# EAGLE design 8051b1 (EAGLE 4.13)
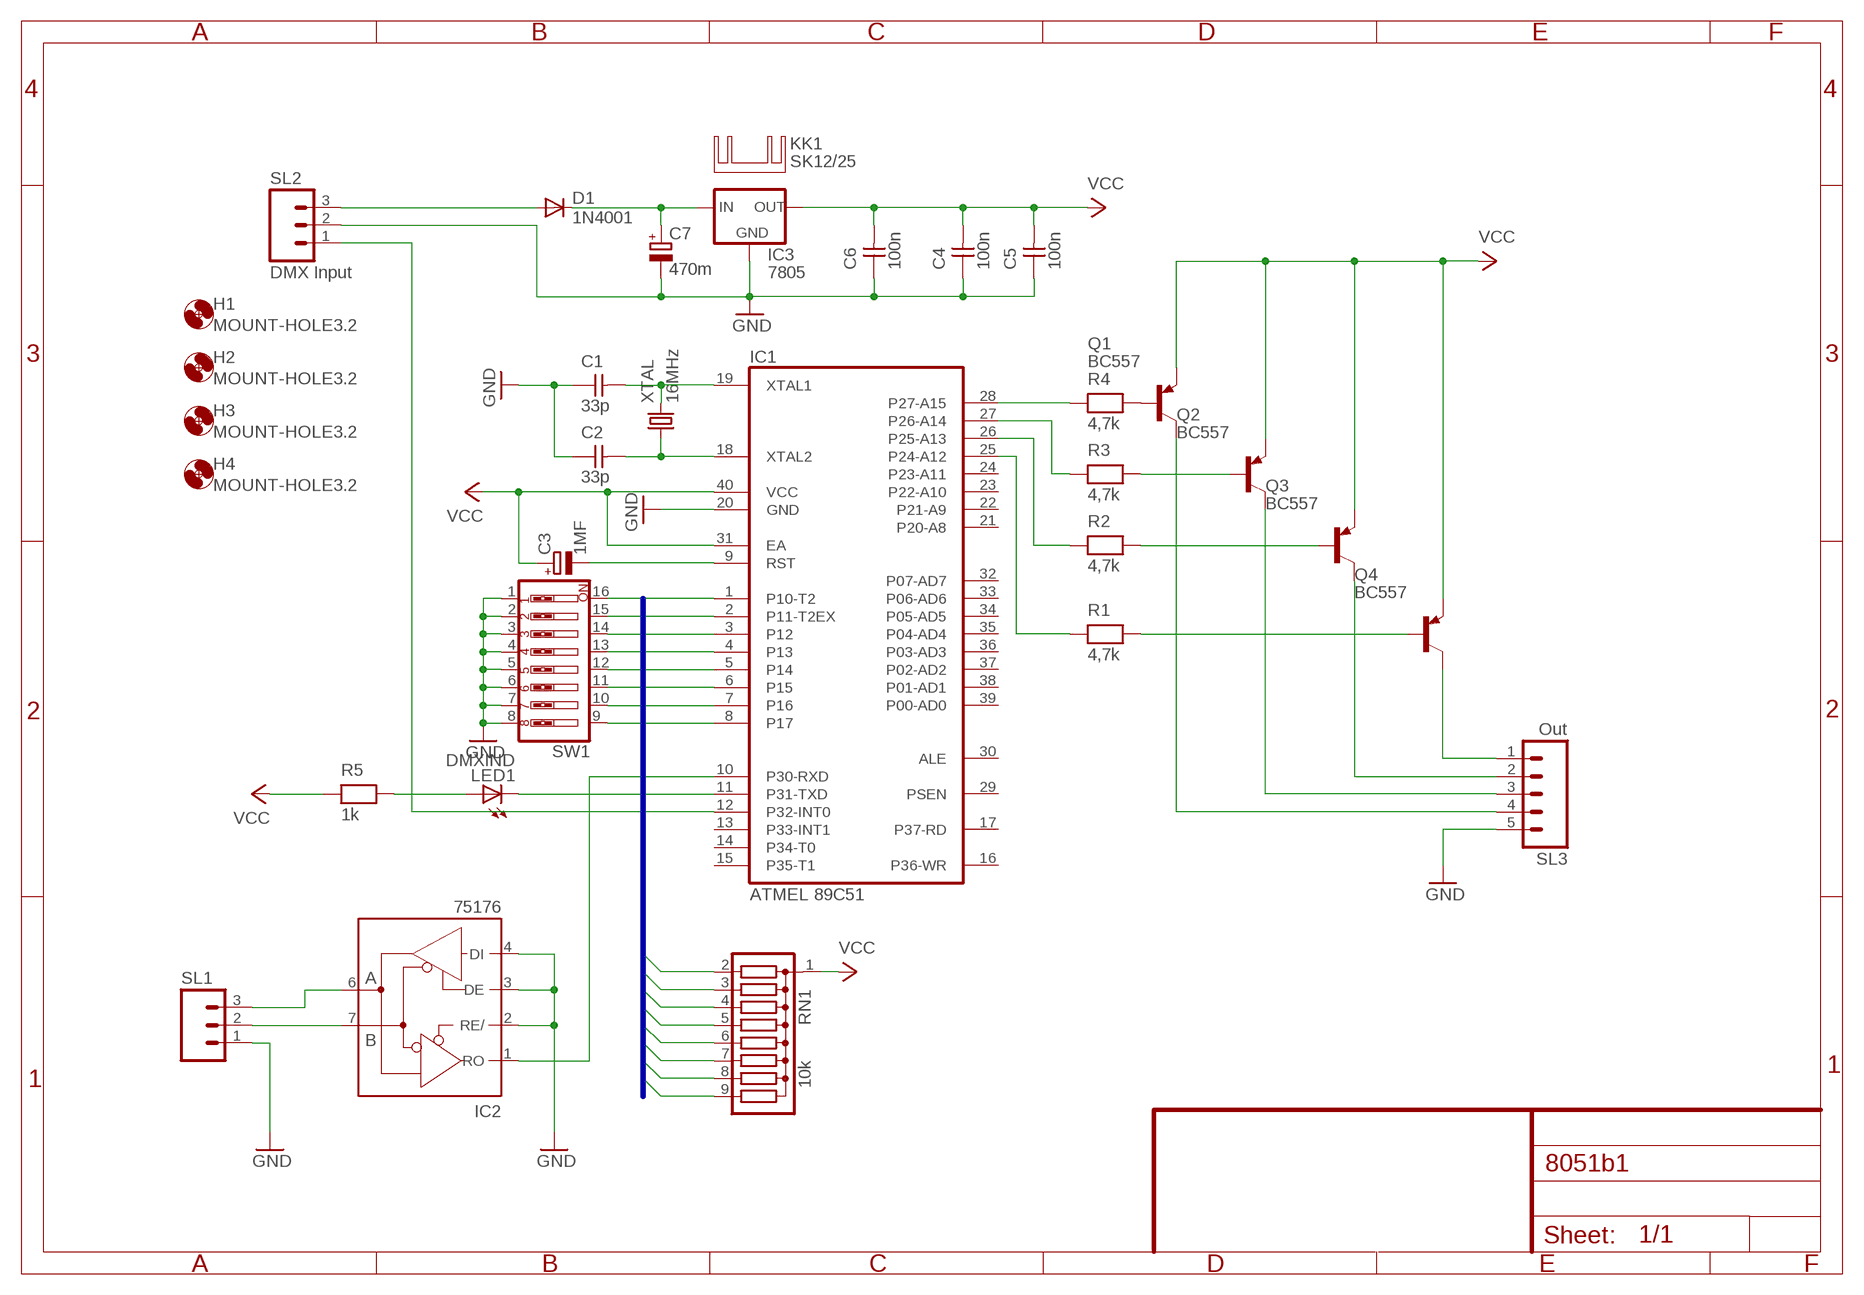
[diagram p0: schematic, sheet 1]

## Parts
C1  33p  CAPNP-5  [C-5]
C2  33p  CAPNP-5  [C-5]
C3  1MF  CPOL-EUE2-4  [E2-4]
C4  100n  CAPNP-2,5  [C-2,5]
C5  100n  CAPNP-2,5  [C-2,5]
C6  100n  CAPNP-2,5  [C-2,5]
C7  470m  CPOL-EUE5-10.5  [E5-10,5]
D1  1N4001  1N4004  [DO41-10]
H1  MOUNT-HOLE3.2  [3,2]
H2  MOUNT-HOLE3.2  [3,2]
H3  MOUNT-HOLE3.2  [3,2]
H4  MOUNT-HOLE3.2  [3,2]
IC1  ATMEL 89C51  8051  [DIL40]
IC2  75176  MAX481CPA  [DIL08]
IC3  7805  78XXL  [78XXL]
KK1  SK12/25  [SK12/25]
LED1  DMXIND  LED3MM  [LED3MM]
Q1  BC557  [TO92]
Q2  BC557  [TO92]
Q3  BC557  [TO92]
Q4  BC557  [TO92]
R1  4,7k  RESEU-10  [R-10]
R2  4,7k  RESEU-10  [R-10]
R3  4,7k  RESEU-10  [R-10]
R4  4,7k  RESEU-10  [R-10]
R5  1k  RESEU-10  [R-10]
RN1  10k  G08R  [SIL9]
SL1  M03  [03P]
SL2  DMX Input  M03  [03P]
SL3  Out  M05  [05P]
SW1  SW_DIP-8  [EDG-08]
XTAL  16MHz  CRYTALHC18U-V  [HC18U-V]

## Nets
DIP1: IC1.1(P10-T2) RN1.2 SW1.16
DIP2: IC1.2(P11-T2EX) RN1.3 SW1.15
DIP3: IC1.3(P12) RN1.4 SW1.14
DIP4: IC1.4(P13) RN1.5 SW1.13
DIP5: IC1.5(P14) RN1.6 SW1.12
DIP6: IC1.6(P15) RN1.7 SW1.11
DIP7: IC1.7(P16) RN1.8 SW1.10
DIP8: IC1.8(P17) RN1.9 SW1.9
DMX+: IC2.6(A) SL1.3
DMX-: IC2.7(B) SL1.2
DMXIND: IC1.11(P31-TXD) LED1.K(C)
EXT0: IC1.12(P32-INT0) SL2.1
GND: C1.1 C2.1 C4.1 C5.1 C6.1 C7.- IC1.20(GND) IC2.2(RE/) IC2.3(DE) IC2.4(DI) IC3.GND SL1.1 SL2.2 SL3.5 SW1.1 SW1.2 SW1.3 SW1.4 SW1.5 SW1.6 SW1.7 SW1.8
N$1: C1.2 IC1.19(XTAL1) XTAL.2
N$2: C2.2 IC1.18(XTAL2) XTAL.1
N$3: Q1.2(B) R4.2
N$4: LED1.A R5.2
N$13: C7.+ D1.C IC3.IN
N$14: D1.A SL2.3
N$19: Q2.2(B) R3.2
N$20: Q3.2(B) R2.2
N$21: Q4.2(B) R1.2
OUT1: IC1.25(P24-A12) R1.1
OUT2: IC1.26(P25-A13) R2.1
OUT3: IC1.27(P26-A14) R3.1
OUT4: IC1.28(P27-A15) R4.1
RESET: C3.- IC1.9(RST)
RXD: IC1.10(P30-RXD) IC2.1(RO)
TREIBEROUT1: Q4.3(C) SL3.1
TREIBEROUT2: Q3.3(C) SL3.2
TREIBEROUT3: Q2.3(C) SL3.3
TREIBEROUT4: Q1.3(C) SL3.4
VCC: C3.+ C4.2 C5.2 C6.2 IC1.31(EA) IC1.40(VCC) IC3.OUT Q1.1(E) Q2.1(E) Q3.1(E) Q4.1(E) R5.1 RN1.1
Unconnected: IC1.13(P33-INT1) IC1.14(P34-T0) IC1.15(P35-T1) IC1.16(P36-WR) IC1.17(P37-RD) IC1.21(P20-A8) IC1.22(P21-A9) IC1.23(P22-A10) IC1.24(P23-A11) IC1.29(PSEN) IC1.30(ALE) IC1.32(P07-AD7) IC1.33(P06-AD6) IC1.34(P05-AD5) IC1.35(P04-AD4) IC1.36(P03-AD3) IC1.37(P02-AD2) IC1.38(P01-AD1) IC1.39(P00-AD0)

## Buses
B$1

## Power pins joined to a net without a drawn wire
GND: IC2.5(GND)
VCC: IC2.8(VCC)

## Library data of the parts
C1 C2 = discrete:CAPNP-5
C3 C7 = rcl:CPOL-EU: POLARIZED CAPACITOR, European symbol
C4-C6 = discrete:CAPNP-2,5
D1 = diode:1N4004: DIODE
H1-H4 = holes:MOUNT-HOLE: MOUNTING HOLE with drill center marker
IC1 = micro-intel:8051: MICROCOMPUTER/PERIPHERAL DEVICE
IC2 = maxim:MAX481CPA: RS485 TRANSEIVER
IC3 = v-reg:78XXL: VOLTAGE REGULATOR
KK1 = heatsink:SK12/25: HEATSINK
LED1 = led:LED: LED
Q1-Q4 = transistor-pnp:BC557: PNP Transistor
R1-R5 = discrete:RESEU-10
RN1 = resistor-sil:G08R: SIL RESISTOR
SL1 SL2 = con-amp-quick:M03: AMP QUICK CONNECTOR
SL3 = con-amp-quick:M05: AMP QUICK CONNECTOR
SW1 = special:SW_DIP-8: DIP SWITCH
XTAL = crystal:CRYTAL: CRYSTAL

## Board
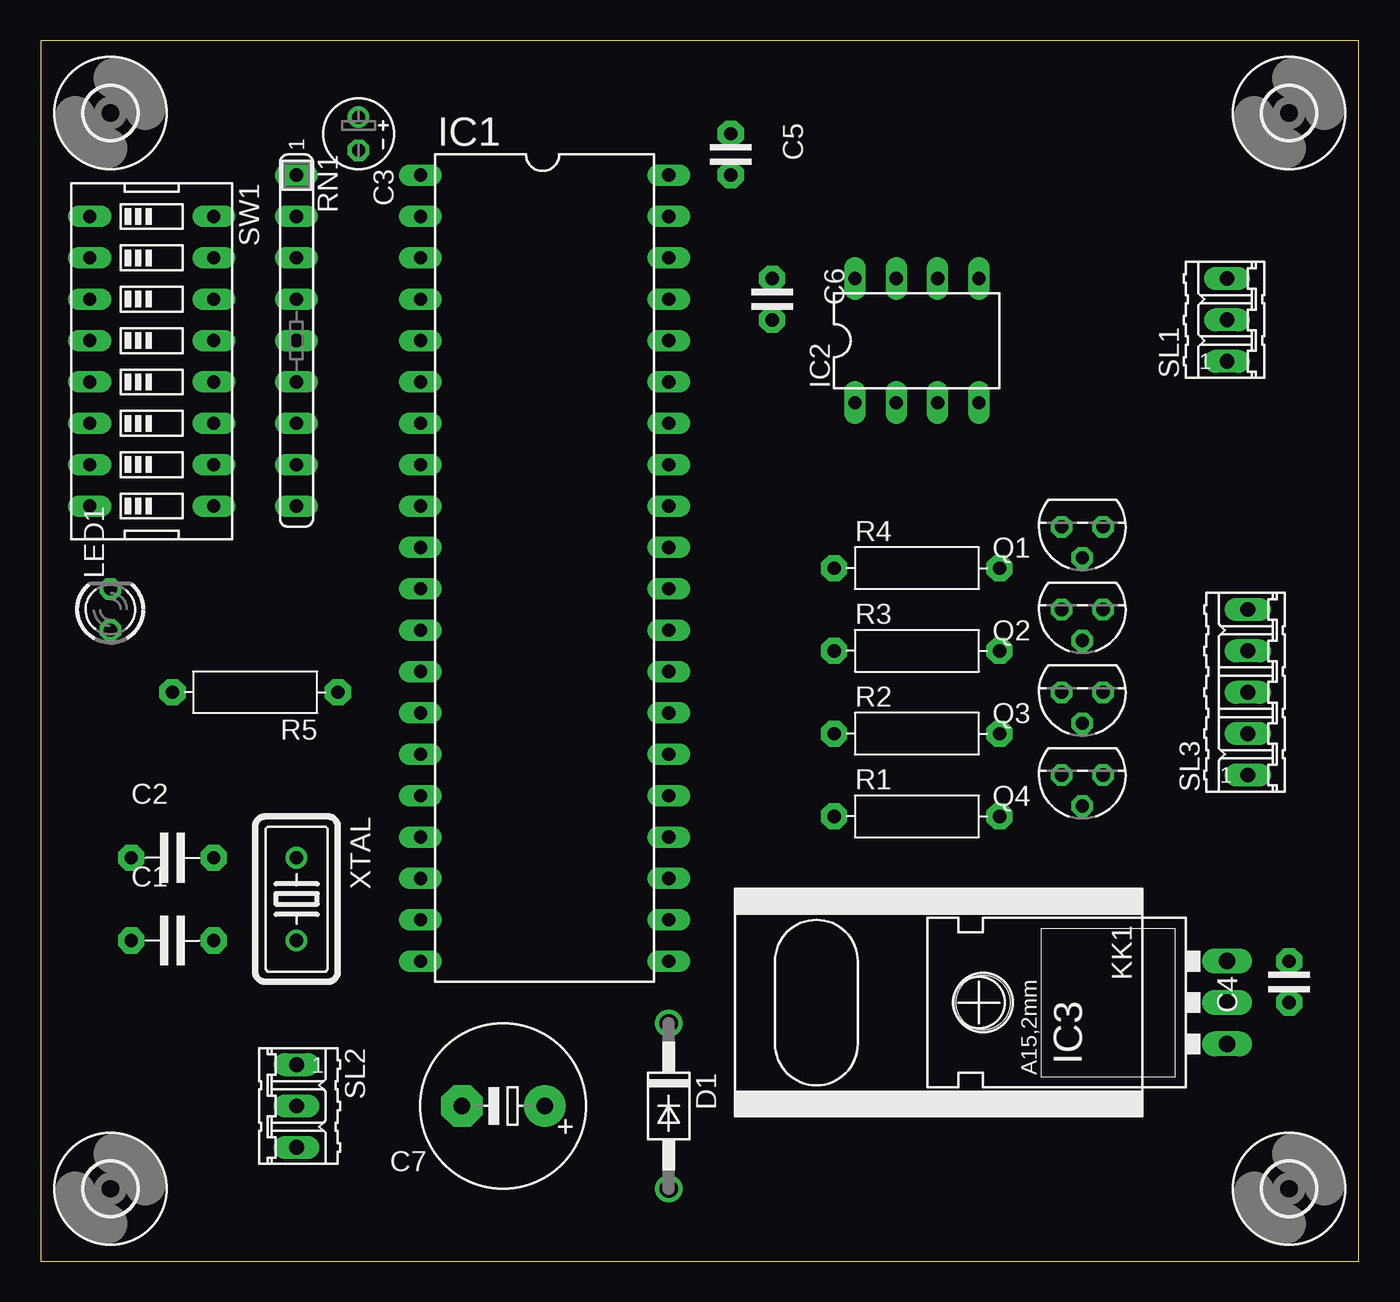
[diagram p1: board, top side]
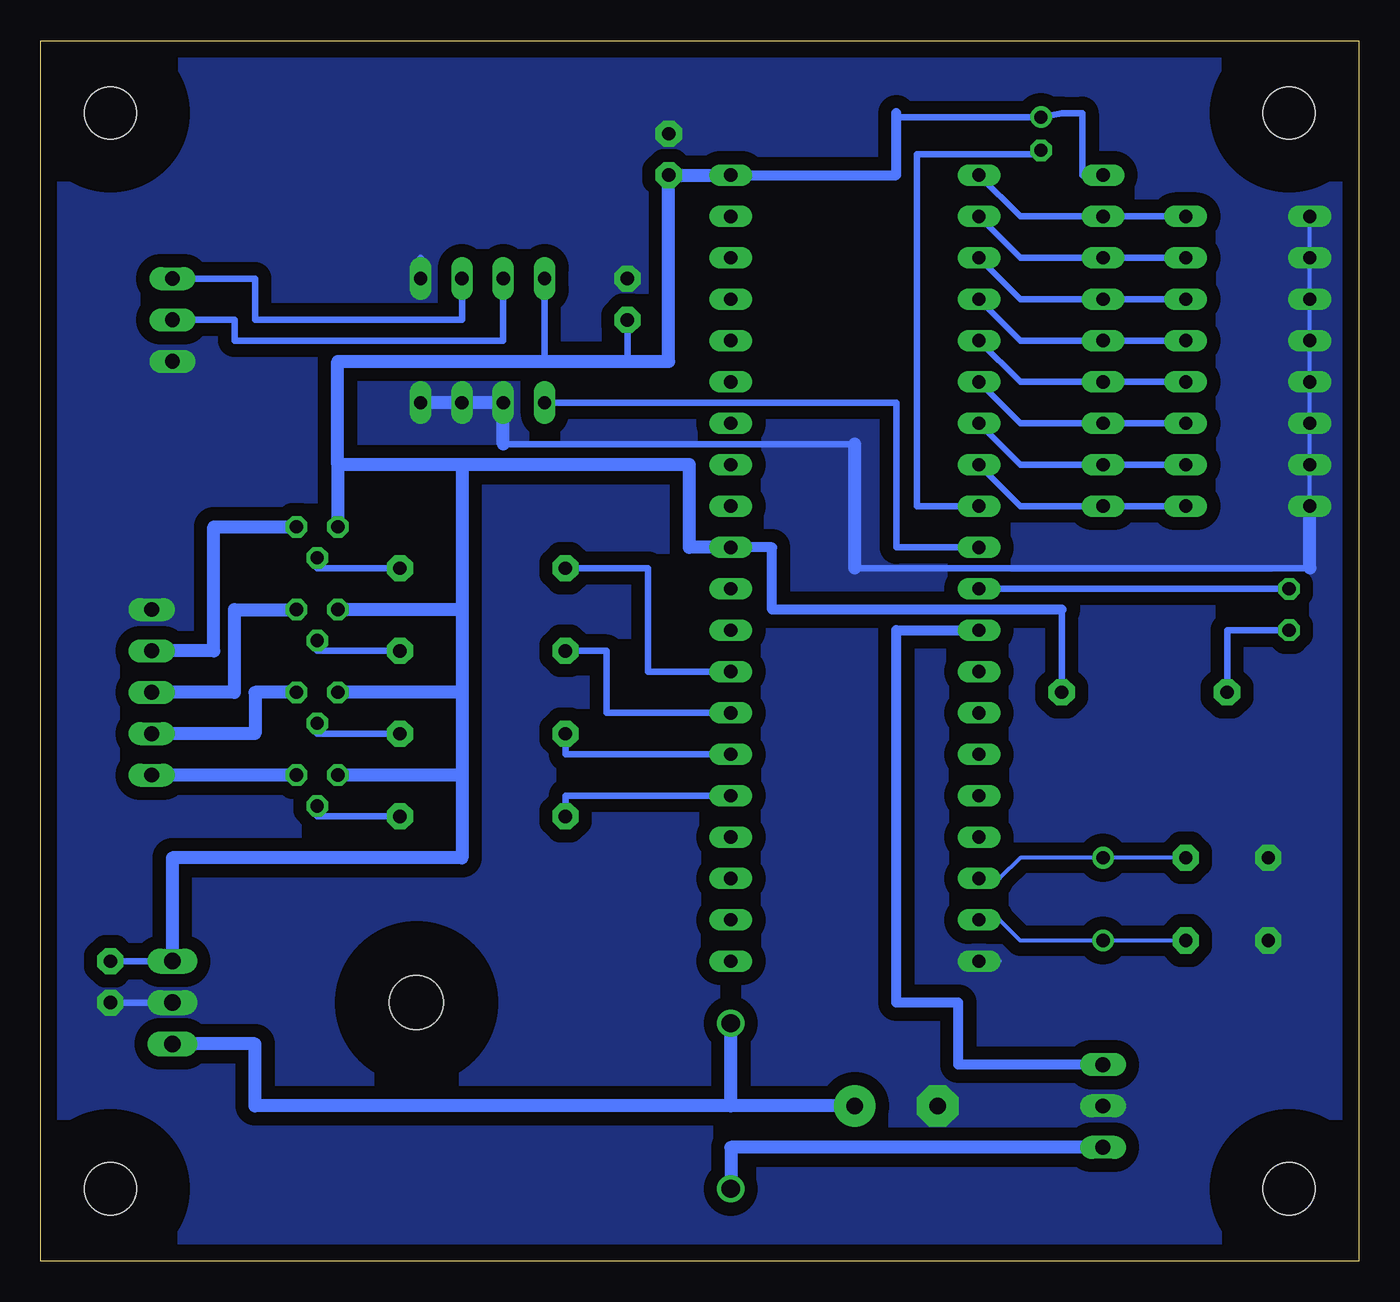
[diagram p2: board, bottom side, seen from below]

Size 80.95 x 74.92 mm. Coordinates in mm from the lower left corner, seen from the top.
Outline: 0,0 80.95,0 80.95,74.92 0,74.92 0,0
Copper layers (1*16): Top 0.035mm / dielectric 1.5mm / Bottom 0.035mm
Design rules "default": minimum track width 10mil, minimum drill 24mil, track to track 8mil, track to pad 8mil, pad to pad 8mil, via to via 8mil, smd to smd 8mil, copper to edge 40mil, drill to drill 8mil, minimum pad ring 10mil, minimum via ring 8mil, stop-mask expansion 4mil, vias tented up to drill 0mil, thermal gap 10mil

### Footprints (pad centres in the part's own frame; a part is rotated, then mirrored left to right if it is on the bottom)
C-5 = drill 0.813 pad 1.6 octagon: 1 -2.54,0; 2 2.54,0
E2-4 = drill 0.813 pad 1.27 round: + -1.016,0 | drill 0.813 pad 1.27 octagon: - 1.016,0
C-2,5 = drill 0.813 pad 1.6 octagon: 1 -1.27,0; 2 1.27,0
E5-10,5 = drill 1.016 pad 2.54 round: + -2.54,0 | drill 1.016 pad 2.54 octagon: - 2.54,0
DO41-10 = drill 1.118 round: A 5.08,0; C -5.08,0
3,2 = hole 3.2: 0,0
DIL40 = drill 0.813 long: 1 -24.13,-7.62; 2 -21.59,-7.62; 3 -19.05,-7.62; 4 -16.51,-7.62; 5 -13.97,-7.62; 6 -11.43,-7.62; 7 -8.89,-7.62; 8 -6.35,-7.62; 9 -3.81,-7.62; 10 -1.27,-7.62; 11 1.27,-7.62; 12 3.81,-7.62; 13 6.35,-7.62; 14 8.89,-7.62; 15 11.43,-7.62; 16 13.97,-7.62; 17 16.51,-7.62; 18 19.05,-7.62; 19 21.59,-7.62; 20 24.13,-7.62; 21 24.13,7.62; 22 21.59,7.62; 23 19.05,7.62; 24 16.51,7.62; 25 13.97,7.62; 26 11.43,7.62; 27 8.89,7.62; 28 6.35,7.62; 29 3.81,7.62; 30 1.27,7.62; 31 -1.27,7.62; 32 -3.81,7.62; 33 -6.35,7.62; 34 -8.89,7.62; 35 -11.43,7.62; 36 -13.97,7.62; 37 -16.51,7.62; 38 -19.05,7.62; 39 -21.59,7.62; 40 -24.13,7.62
DIL08 = drill 0.813 long: 1 -3.81,-3.81; 2 -1.27,-3.81; 3 1.27,-3.81; 4 3.81,-3.81; 5 3.81,3.81; 6 1.27,3.81; 7 -1.27,3.81; 8 -3.81,3.81
78XXL = drill 1.016 long: GND 0,-3.81; IN -2.54,-3.81; OUT 2.54,-3.81 | hole 3.302: 0,11.176
LED3MM = drill 0.813 octagon: A -1.27,0; K 1.27,0
TO92 = drill 0.813 octagon: 1 1.27,0; 2 0,1.905; 3 -1.27,0
R-10 = drill 0.813 pad 1.6 octagon: 1 -5.08,0; 2 5.08,0
SIL9 = drill 0.813 long: 1 -10.16,0; 2 -7.62,0; 3 -5.08,0; 4 -2.54,0; 5 0,0; 6 2.54,0; 7 5.08,0; 8 7.62,0; 9 10.16,0
03P = drill 0.914 long: 1 -2.54,0; 2 0,0; 3 2.54,0
05P = drill 0.914 long: 1 -5.08,0; 2 -2.54,0; 3 0,0; 4 2.54,0; 5 5.08,0
EDG-08 = drill 0.813 long: 1 -8.89,-3.81; 2 -6.35,-3.81; 3 -3.81,-3.81; 4 -1.27,-3.81; 5 1.27,-3.81; 6 3.81,-3.81; 7 6.35,-3.81; 8 8.89,-3.81; 9 8.89,3.81; 10 6.35,3.81; 11 3.81,3.81; 12 1.27,3.81; 13 -1.27,3.81; 14 -3.81,3.81; 15 -6.35,3.81; 16 -8.89,3.81
HC18U-V = drill 0.813 round: 1 -2.54,0; 2 2.54,0

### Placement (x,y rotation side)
C1  8.09,19.68 0 top
C2  8.09,24.76 0 top
C3  19.52,69.21 270 top
C4  76.67,17.14 90 top
C5  42.38,67.94 270 top
C6  44.92,59.05 270 top
C7  28.41,9.52 180 top
D1  38.57,9.52 270 top
H1  4.28,4.44 0 top
H2  4.28,70.48 0 top
H3  76.67,70.48 0 top
H4  76.67,4.44 0 top
IC1  30.95,42.54 270 top
IC2  53.81,56.51 0 top
IC3  69.05,15.87 90 top
KK1  52.54,15.87 180 top
LED1  4.28,40 90 top
Q1  63.97,45.08 180 top
Q2  63.97,40 180 top
Q3  63.97,34.92 180 top
Q4  63.97,29.84 180 top
R1  53.81,27.3 0 top
R2  53.81,32.38 0 top
R3  53.81,37.46 0 top
R4  53.81,42.54 0 top
R5  13.17,34.92 180 top
RN1  15.71,56.51 270 top
SL1  72.86,57.78 90 top
SL2  15.71,9.52 270 top
SL3  74.13,34.92 90 top
SW1  6.82,55.24 270 top
XTAL  15.71,22.22 270 top

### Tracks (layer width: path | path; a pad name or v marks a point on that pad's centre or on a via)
DIP1
  Bottom 0.406: IC1.1 20.79,64.13 RN1.2 SW1.16
DIP2
  Bottom 0.406: IC1.2 20.79,61.59 RN1.3 SW1.15
DIP3
  Bottom 0.406: IC1.3 20.79,59.05 RN1.4 SW1.14
DIP4
  Bottom 0.406: IC1.4 20.79,56.51 RN1.5 SW1.13
DIP5
  Bottom 0.406: IC1.5 20.79,53.97 RN1.6 SW1.12
DIP6
  Bottom 0.406: IC1.6 20.79,51.43 RN1.7 SW1.11
DIP7
  Bottom 0.406: IC1.7 20.79,48.89 RN1.8 SW1.10
DIP8
  Bottom 0.406: SW1.9 RN1.9 20.79,46.35 IC1.8
DMX+
  Bottom 0.406: SL1.3 67.78,60.32 67.78,57.78 55.08,57.78 IC2.6
DMX-
  Bottom 0.406: SL1.2 69.05,57.78 69.05,56.51 52.54,56.51 IC2.7
DMXIND
  Bottom 0.406: LED1.K IC1.11
EXT0
  Bottom 0.61: SL2.1 24.6,12.06 24.6,15.87 28.41,15.87 28.41,38.73 IC1.12
GND
  Bottom 0.254: SW1.1 SW1.2 SW1.3 SW1.4 SW1.5 SW1.6 SW1.7 SW1.8 | IC1.20 22.06,18.41
  Bottom 0.406: IC3.GND C4.1 | 30.95,50.16 52.54,50.16 | 3.01,42.54 30.95,42.54 | IC2.5 57.62,61.59
  Bottom 0.813: 52.54,50.16 IC2.2 IC2.3 IC2.4 | 30.95,42.54 30.95,50.16 | 3.01,42.54 SW1.8
  pour Bottom (isolate 0.813, no thermals): 1.74,74.29 80.48,74.29 80.48,0.63 0.47,0.63 0.47,74.29
N$1
  Bottom 0.254: C1.2 XTAL.2 20.79,19.68 22.06,20.95 IC1.19
N$2
  Bottom 0.254: C2.2 XTAL.1 20.79,24.76 22.06,23.49 IC1.18
N$3
  Bottom 0.406: Q1.2 63.97,42.54 R4.2
N$4
  Bottom 0.406: LED1.A 8.09,38.73 R5.2
N$13
  Bottom 0.813: 38.57,9.52 67.78,9.52 67.78,13.33 IC3.IN | C7.+ 38.57,9.52 | 38.57,9.52 D1.C
N$14
  Bottom 0.813: D1.A 38.57,6.98 SL2.3
N$19
  Bottom 0.406: Q2.2 63.97,37.46 R3.2
N$20
  Bottom 0.406: R2.2 63.97,32.38 Q3.2
N$21
  Bottom 0.406: Q4.2 63.97,27.3 R1.2
OUT1
  Bottom 0.406: IC1.25 48.73,28.57 R1.1
OUT2
  Bottom 0.406: IC1.26 48.73,31.11 R2.1
OUT3
  Bottom 0.406: IC1.27 46.19,33.65 46.19,37.46 R3.1
OUT4
  Bottom 0.406: IC1.28 43.65,36.19 43.65,42.54 R4.1
RESET
  Bottom 0.254: IC1.9 24.6,46.35
  Bottom 0.406: IC1.9 27.14,46.35 27.14,67.94 19.52,67.94 C3.-
RXD
  Bottom 0.406: IC2.1 28.41,52.7 28.41,43.81 IC1.10
TREIBEROUT1
  Bottom 0.813: Q4.3 SL3.1
TREIBEROUT2
  Bottom 0.813: SL3.2 67.78,32.38 67.78,34.92 Q3.3
TREIBEROUT3
  Bottom 0.813: SL3.3 69.05,34.92 69.05,40 Q2.3
TREIBEROUT4
  Bottom 0.813: SL3.4 70.32,37.46 70.32,45.08 Q1.3
VCC
  Bottom 0.406: IC3.OUT C4.2 | R5.1 18.25,40 | 50,55.24 IC2.8 | 44.92,55.24 C6.2 | RN1.1 16.98,66.67 16.98,70.48 18.25,70.48 C3.+ 28.41,70.23
  Bottom 0.61: 18.25,40 36.03,40 36.03,43.81 IC1.31 | 28.41,70.48 28.41,70.23 28.41,66.67 IC1.40
  Bottom 0.813: IC1.40 C5.2 42.38,55.24 44.92,55.24 50,55.24 62.7,55.24 62.7,48.89 | IC3.OUT 72.86,24.76 55.08,24.76 55.08,29.84 | 55.08,34.92 55.08,29.84 | 55.08,40 55.08,34.92 | 55.08,48.89 55.08,40 | 55.08,48.89 62.7,48.89 | 62.7,48.89 Q1.1 | 55.08,40 Q2.1 | 55.08,34.92 Q3.1 | 55.08,29.84 Q4.1 | IC1.31 41.11,43.81 41.11,48.89 55.08,48.89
